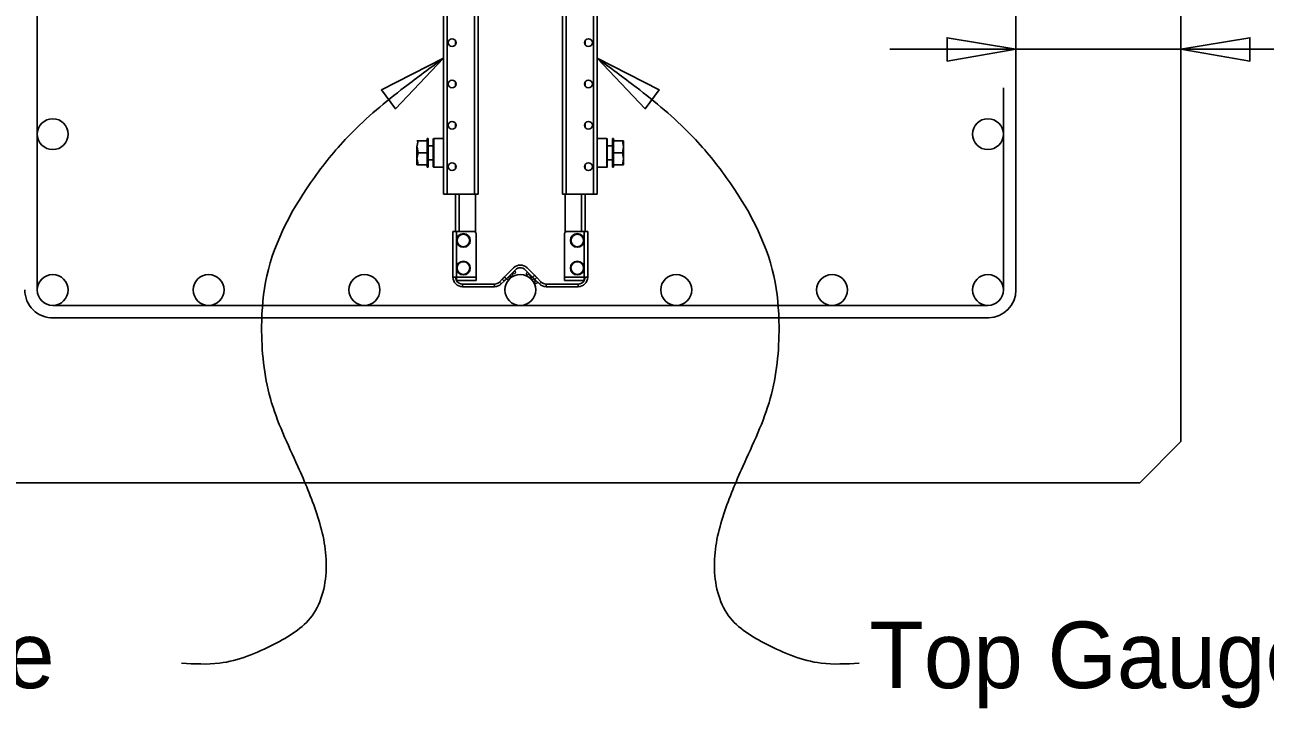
# Model space of a CAD drawing. Extents: x 0 to 36.1, y -3.7 to 15.
# Drawn here: x 2.543 to 4.42, y 5.937 to 6.972 of the extents above; entities that cross this region are included whole.
import ezdxf

# ---------------------------------------------------------------- set-up
doc = ezdxf.new("R2010")
doc.units = 0
for name, color, linetype in [('Dimension', 7, 'Continuous'), ('Leader', 7, 'Continuous'), ('Miscellaneous', 7, 'Continuous'), ('PileConc', 7, 'Continuous'), ('PrestressSteel', 7, 'Continuous')]:
    doc.layers.add(name, color=color, linetype=linetype)

msp = doc.modelspace()

# ---------------------------------------------------------------- linework, layer by layer
at = {"layer": 'Dimension'}
for p, q in [((3.8524, 6.9353), (4.043, 6.9353)), ((4.043, 6.9353), (4.293, 6.9353)), ((4.293, 6.9353), (5.1697, 6.9353))]:
    msp.add_line(p, q, dxfattribs=at)
for points in [[(4.043, 6.9353), (3.9389, 6.9529), (3.9389, 6.9176)], [(4.293, 6.9353), (4.3972, 6.9176), (4.3972, 6.9529)], [(3.1768, 6.9218), (3.0828, 6.8737), (3.1039, 6.8454)], [(3.4093, 6.9218), (3.4822, 6.8454), (3.5033, 6.8737)]]:
    msp.add_lwpolyline(points, close=True, dxfattribs=at)
at = {"layer": 'Leader'}
for points in [[(2.7804, 6.0056), (2.8378, 6.0056), (2.9204, 6.0343), (2.9778, 6.0774), (2.9994, 6.1527), (2.985, 6.2317), (2.9563, 6.3035), (2.9147, 6.4066), (2.9015, 6.5152), (2.9094, 6.592), (2.9814, 6.7414), (3.0353, 6.8061), (3.1178, 6.8779), (3.1768, 6.9218)], [(3.8057, 6.0056), (3.7483, 6.0056), (3.6657, 6.0343), (3.6083, 6.0774), (3.5867, 6.1527), (3.6011, 6.2317), (3.6298, 6.3035), (3.6714, 6.4066), (3.6846, 6.5152), (3.6767, 6.592), (3.6047, 6.7414), (3.5508, 6.8061), (3.4683, 6.8779), (3.4093, 6.9218)]]:
    msp.add_spline(points, degree=3, dxfattribs=at)
at = {"layer": 'Miscellaneous'}
for p, q in [((3.1768, 6.7159), (3.1768, 7.7123)), ((3.4093, 6.7159), (3.4093, 7.7123)), ((3.1821, 6.7159), (3.1821, 7.2312)), ((3.2239, 6.7159), (3.2239, 7.2284)), ((3.2292, 6.7159), (3.2292, 7.2284)), ((3.3569, 6.7159), (3.3569, 7.2284)), ((3.3622, 6.7159), (3.3622, 7.2284)), ((3.404, 6.7159), (3.404, 7.2312)), ((3.1951, 6.9429), (3.1951, 6.9481)), ((3.391, 6.9429), (3.391, 6.9481)), ((3.1951, 6.8802), (3.1951, 6.8855)), ((3.391, 6.8802), (3.391, 6.8855)), ((3.1951, 6.8176), (3.1951, 6.8229)), ((3.391, 6.8176), (3.391, 6.8229)), ((3.1383, 6.7968), (3.1366, 6.7876)), ((3.1366, 6.7968), (3.1383, 6.7968)), ((3.1519, 6.7968), (3.1383, 6.7968)), ((3.1515, 6.7968), (3.1521, 6.8004)), ((3.1519, 6.7968), (3.1519, 6.7785)), ((3.1521, 6.8004), (3.1533, 6.8004)), ((3.1521, 6.8004), (3.1521, 6.7566)), ((3.1533, 6.7566), (3.1533, 6.8004)), ((3.1613, 6.7995), (3.1613, 6.7575)), ((3.162, 6.8002), (3.1768, 6.8002)), ((3.162, 6.7568), (3.162, 6.8002)), ((3.4241, 6.8002), (3.4093, 6.8002)), ((3.4241, 6.7568), (3.4241, 6.8002)), ((3.4247, 6.7995), (3.4247, 6.7575)), ((3.434, 6.8004), (3.4327, 6.8004)), ((3.4327, 6.7566), (3.4327, 6.8004)), ((3.4346, 6.7968), (3.434, 6.8004)), ((3.434, 6.8004), (3.434, 6.7566)), ((3.4341, 6.7968), (3.4341, 6.7785)), ((3.4341, 6.7968), (3.4478, 6.7968)), ((3.4478, 6.7968), (3.4494, 6.7876)), ((3.4494, 6.7968), (3.4478, 6.7968)), ((3.4494, 6.7876), (3.4494, 6.7968)), ((3.1366, 6.7694), (3.1366, 6.7876)), ((3.1383, 6.7785), (3.1366, 6.7694)), ((3.1519, 6.7785), (3.1383, 6.7785)), ((3.1519, 6.7785), (3.1519, 6.7602)), ((3.1533, 6.7889), (3.1613, 6.7889)), ((3.4327, 6.7889), (3.4247, 6.7889)), ((3.4341, 6.7785), (3.4341, 6.7602)), ((3.4341, 6.7785), (3.4478, 6.7785)), ((3.4478, 6.7785), (3.4494, 6.7694)), ((3.4494, 6.7694), (3.4494, 6.7876)), ((3.1366, 6.7602), (3.1366, 6.7694)), ((3.1383, 6.7602), (3.1366, 6.7602)), ((3.1519, 6.7602), (3.1383, 6.7602)), ((3.1521, 6.7566), (3.1515, 6.7602)), ((3.1613, 6.7681), (3.1533, 6.7681)), ((3.1951, 6.755), (3.1951, 6.7603)), ((3.391, 6.755), (3.391, 6.7603)), ((3.4247, 6.7681), (3.4327, 6.7681)), ((3.434, 6.7566), (3.4346, 6.7602)), ((3.4341, 6.7602), (3.4478, 6.7602)), ((3.4478, 6.7602), (3.4494, 6.7602)), ((3.4494, 6.7602), (3.4494, 6.7694)), ((3.1533, 6.7566), (3.1521, 6.7566)), ((3.1768, 6.7568), (3.162, 6.7568)), ((3.4093, 6.7568), (3.4241, 6.7568)), ((3.4327, 6.7566), (3.434, 6.7566)), ((3.1821, 6.7159), (3.1768, 6.7159)), ((3.1821, 6.7159), (3.2239, 6.7159)), ((3.1951, 6.6596), (3.1951, 6.7159)), ((3.2004, 6.6596), (3.2004, 6.7159)), ((3.2292, 6.7159), (3.2239, 6.7159)), ((3.2252, 6.6579), (3.2252, 6.7159)), ((3.3569, 6.7159), (3.3622, 6.7159)), ((3.3609, 6.6579), (3.3609, 6.7159)), ((3.404, 6.7159), (3.3622, 6.7159)), ((3.3857, 6.6596), (3.3857, 6.7159)), ((3.391, 6.6596), (3.391, 6.7159)), ((3.404, 6.7159), (3.4093, 6.7159)), ((3.1911, 6.6596), (3.1963, 6.6596)), ((3.1911, 6.5902), (3.1911, 6.6596)), ((3.2214, 6.6596), (3.1963, 6.6596)), ((3.1963, 6.5902), (3.1963, 6.6596)), ((3.2264, 6.5902), (3.2264, 6.6546)), ((3.3597, 6.5902), (3.3597, 6.6546)), ((3.3647, 6.6596), (3.3897, 6.6596)), ((3.3897, 6.5902), (3.3897, 6.6596)), ((3.395, 6.6596), (3.3897, 6.6596)), ((3.395, 6.5902), (3.395, 6.6596)), ((3.1963, 6.5902), (3.1911, 6.5902)), ((3.1963, 6.585), (3.1963, 6.5902)), ((3.1963, 6.5902), (3.2264, 6.5902)), ((3.2264, 6.5902), (3.2264, 6.585)), ((3.2692, 6.5907), (3.2828, 6.6043)), ((3.2721, 6.5879), (3.2692, 6.5907)), ((3.2857, 6.6015), (3.2721, 6.5879)), ((3.2771, 6.5911), (3.2786, 6.5896)), ((3.2786, 6.5926), (3.2801, 6.5911)), ((3.2811, 6.5951), (3.2802, 6.596)), ((3.2807, 6.5947), (3.2821, 6.5932)), ((3.2827, 6.5967), (3.2842, 6.5953)), ((3.2852, 6.5992), (3.2843, 6.6001)), ((3.2848, 6.5988), (3.2863, 6.5974)), ((3.3116, 6.5902), (3.3004, 6.6015)), ((3.3034, 6.5967), (3.302, 6.5952)), ((3.3039, 6.5979), (3.3031, 6.5971)), ((3.3033, 6.6043), (3.3145, 6.5931)), ((3.3055, 6.5946), (3.3041, 6.5931)), ((3.3091, 6.591), (3.3076, 6.5896)), ((3.311, 6.5909), (3.3101, 6.59)), ((3.3145, 6.5931), (3.3116, 6.5902)), ((3.3597, 6.5902), (3.3597, 6.585)), ((3.3897, 6.5902), (3.3597, 6.5902)), ((3.3897, 6.585), (3.3897, 6.5902)), ((3.3897, 6.5902), (3.395, 6.5902)), ((3.2264, 6.585), (3.1963, 6.585)), ((3.2055, 6.5798), (3.2055, 6.5758)), ((3.254, 6.5798), (3.2055, 6.5798)), ((3.254, 6.5758), (3.2055, 6.5758)), ((3.254, 6.5758), (3.254, 6.5798)), ((3.2657, 6.5872), (3.2614, 6.5828)), ((3.2614, 6.5828), (3.2642, 6.58)), ((3.2685, 6.5843), (3.2642, 6.58)), ((3.2657, 6.5872), (3.2685, 6.5843)), ((3.2717, 6.5875), (3.2726, 6.5866)), ((3.2729, 6.587), (3.2744, 6.5855)), ((3.275, 6.5891), (3.2765, 6.5876)), ((3.3105, 6.5896), (3.3091, 6.5881)), ((3.3126, 6.5875), (3.3111, 6.586)), ((3.3162, 6.5839), (3.3147, 6.5825)), ((3.3152, 6.5867), (3.318, 6.5895)), ((3.3152, 6.5867), (3.3219, 6.58)), ((3.3183, 6.5819), (3.3168, 6.5804)), ((3.318, 6.5895), (3.3247, 6.5828)), ((3.3186, 6.5815), (3.3195, 6.5824)), ((3.3247, 6.5828), (3.3219, 6.58)), ((3.3321, 6.5758), (3.3321, 6.5798)), ((3.3321, 6.5798), (3.3806, 6.5798)), ((3.3321, 6.5758), (3.3806, 6.5758)), ((3.3597, 6.585), (3.3897, 6.585)), ((3.3806, 6.5798), (3.3806, 6.5758))]:
    msp.add_line(p, q, dxfattribs=at)
for points in [[(3.1366, 6.7876), (3.1367, 6.787), (3.1383, 6.7785)], [(3.4494, 6.7876), (3.4494, 6.787), (3.4478, 6.7785)], [(3.1366, 6.7694), (3.1367, 6.7687), (3.1383, 6.7602)], [(3.4494, 6.7694), (3.4494, 6.7687), (3.4478, 6.7602)], [(3.2692, 6.5907), (3.2686, 6.59), (3.2679, 6.5894), (3.2673, 6.5887), (3.2667, 6.5882), (3.2663, 6.5878), (3.266, 6.5874), (3.2658, 6.5872), (3.2657, 6.5872)], [(3.275, 6.5891), (3.2755, 6.5895), (3.2759, 6.5899), (3.2763, 6.5904), (3.2768, 6.5908), (3.2773, 6.5913), (3.2777, 6.5917), (3.2782, 6.5922), (3.2786, 6.5926)], [(3.2786, 6.5896), (3.2787, 6.5898), (3.2789, 6.59), (3.2792, 6.5902), (3.2794, 6.5905), (3.2797, 6.5908), (3.28, 6.5911), (3.2801, 6.5911)], [(3.2801, 6.5911), (3.2804, 6.5915), (3.2807, 6.5918), (3.281, 6.5921), (3.2813, 6.5924), (3.2815, 6.5926), (3.2818, 6.5928), (3.282, 6.593), (3.2821, 6.5932)], [(3.2807, 6.5947), (3.2808, 6.5949), (3.281, 6.595), (3.281, 6.5951), (3.2811, 6.5951)], [(3.2811, 6.5951), (3.2814, 6.5954), (3.2818, 6.5959), (3.2823, 6.5963), (3.2827, 6.5967)], [(3.2842, 6.5953), (3.2845, 6.5956), (3.2848, 6.5959), (3.2851, 6.5962), (3.2854, 6.5965), (3.2857, 6.5967), (3.2859, 6.597), (3.2861, 6.5972), (3.2863, 6.5974)], [(3.2848, 6.5988), (3.285, 6.599), (3.2851, 6.5991), (3.2852, 6.5992), (3.2852, 6.5992)], [(3.302, 6.5952), (3.3021, 6.595), (3.3023, 6.5948), (3.3026, 6.5946), (3.3028, 6.5943), (3.3031, 6.5941), (3.3034, 6.5938), (3.3037, 6.5934), (3.3041, 6.5931)], [(3.3031, 6.5971), (3.3031, 6.597), (3.3032, 6.597), (3.3033, 6.5968), (3.3034, 6.5967)], [(3.3055, 6.5946), (3.306, 6.5941), (3.3064, 6.5937), (3.3069, 6.5933), (3.3073, 6.5928), (3.3078, 6.5923), (3.3082, 6.5919), (3.3087, 6.5915), (3.3091, 6.591)], [(3.3101, 6.59), (3.3102, 6.5899), (3.3102, 6.5899), (3.3104, 6.5897), (3.3105, 6.5896)], [(3.3116, 6.5902), (3.3123, 6.5895), (3.313, 6.5889), (3.3136, 6.5883), (3.3141, 6.5877), (3.3146, 6.5873), (3.3149, 6.587), (3.3151, 6.5868), (3.3152, 6.5867)], [(3.318, 6.5895), (3.3179, 6.5896), (3.3177, 6.5898), (3.3174, 6.5901), (3.317, 6.5906), (3.3164, 6.5911), (3.3158, 6.5917), (3.3152, 6.5924), (3.3145, 6.5931)], [(3.2685, 6.5843), (3.2686, 6.5844), (3.2688, 6.5846), (3.2691, 6.5849), (3.2696, 6.5854), (3.2701, 6.5859), (3.2707, 6.5865), (3.2714, 6.5872), (3.2721, 6.5879)], [(3.2726, 6.5866), (3.2726, 6.5866), (3.2727, 6.5867), (3.2728, 6.5868), (3.2729, 6.587)], [(3.2744, 6.5855), (3.2746, 6.5857), (3.2748, 6.5859), (3.275, 6.5861), (3.2753, 6.5863), (3.2756, 6.5866), (3.2759, 6.5869), (3.2762, 6.5872), (3.2765, 6.5876)], [(3.3076, 6.5896), (3.3079, 6.5892), (3.3083, 6.5889), (3.3086, 6.5886), (3.3088, 6.5883), (3.3091, 6.5881)], [(3.3091, 6.5881), (3.3092, 6.5879), (3.3094, 6.5877), (3.3097, 6.5875), (3.3099, 6.5872), (3.3102, 6.587), (3.3105, 6.5867), (3.3108, 6.5863), (3.3111, 6.586)], [(3.3126, 6.5875), (3.313, 6.5871), (3.3135, 6.5866), (3.3139, 6.5862), (3.3144, 6.5857), (3.3148, 6.5853), (3.3153, 6.5848), (3.3157, 6.5844), (3.3162, 6.5839)], [(3.3147, 6.5825), (3.315, 6.5821), (3.3153, 6.5818), (3.3156, 6.5815), (3.3159, 6.5812), (3.3162, 6.581), (3.3164, 6.5807), (3.3166, 6.5805), (3.3168, 6.5804)], [(3.3183, 6.5819), (3.3184, 6.5817), (3.3185, 6.5816), (3.3186, 6.5815), (3.3186, 6.5815)]]:
    msp.add_lwpolyline(points, dxfattribs=at)
for centre, radius in [((3.1898, 6.9455), 0.00589), ((3.3962, 6.9455), 0.00589), ((3.1898, 6.8829), 0.00589), ((3.3962, 6.8829), 0.00589), ((3.1898, 6.8203), 0.00589), ((3.3962, 6.8203), 0.00589), ((3.1898, 6.7576), 0.00589), ((3.3962, 6.7576), 0.00589), ((3.2069, 6.6458), 0.0104), ((3.2069, 6.6458), 0.00951), ((3.3792, 6.6458), 0.0104), ((3.3792, 6.6458), 0.00951), ((3.2069, 6.604), 0.0104), ((3.2069, 6.604), 0.00951), ((3.3792, 6.604), 0.0104), ((3.3792, 6.604), 0.00951)]:
    msp.add_circle(centre, radius, dxfattribs=at)
for centre, radius, start, end in [((3.162, 6.7995), 0.000668, 90, 180), ((3.4241, 6.7995), 0.000668, 0, 90), ((3.162, 6.7575), 0.000668, 180, 270), ((3.4241, 6.7575), 0.000668, 270, 0), ((3.2214, 6.6546), 0.00501, 0, 90), ((3.3647, 6.6546), 0.00501, 90, 180), ((3.293, 6.5941), 0.0144, 45, 135), ((3.2055, 6.5902), 0.0144, 180, 270), ((3.2055, 6.5902), 0.0104, 180, 208.3576), ((3.293, 6.5941), 0.0104, 45, 135), ((3.3806, 6.5902), 0.0144, 270, 0), ((3.3806, 6.5902), 0.0104, 331.6424, 0), ((3.2055, 6.5902), 0.0104, 210.265, 270), ((3.254, 6.5902), 0.0104, 270, 315), ((3.254, 6.5902), 0.0144, 270, 315), ((3.3321, 6.5902), 0.0144, 225, 270), ((3.3321, 6.5902), 0.0104, 225, 270), ((3.3806, 6.5902), 0.0104, 270, 329.735)]:
    msp.add_arc(centre, radius, start, end, dxfattribs=at)
at = {"layer": 'PileConc'}
for p, q in [((4.293, 8.2161), (4.293, 6.3411)), ((4.293, 6.3411), (4.2305, 6.2786)), ((2.3555, 6.2786), (4.2305, 6.2786))]:
    msp.add_line(p, q, dxfattribs=at)
at = {"layer": 'PrestressSteel'}
for p, q in [((2.5618, 7.9864), (2.5618, 6.5708)), ((4.043, 7.9864), (4.043, 6.5708)), ((4.0242, 6.8772), (4.0242, 6.5708)), ((2.5861, 6.5474), (4, 6.5474)), ((2.5862, 6.5286), (4.0017, 6.5286))]:
    msp.add_line(p, q, dxfattribs=at)
for centre in [(2.5853, 6.8068), (4.0008, 6.8068), (2.5853, 6.5708), (2.8212, 6.5708), (3.0571, 6.5708), (3.293, 6.5708), (3.529, 6.5708), (3.7649, 6.5708), (4.0008, 6.5708)]:
    msp.add_circle(centre, 0.0234, dxfattribs=at)
for centre, start, end in [((2.5853, 6.5708), 180, 271.2723), ((4.0008, 6.5708), 271.2723, 0)]:
    msp.add_arc(centre, 0.0423, start, end, dxfattribs=at)

# ---------------------------------------------------------------- texts
at = {"layer": 'Dimension'}
for s, p in [('Tip Gauge', (1.9587, 5.9677)), ('Top Gauge', (3.8214, 5.9677))]:
    msp.add_text(s, height=0.1008, dxfattribs=at).set_placement(p)

doc.saveas('drawing.dxf')
